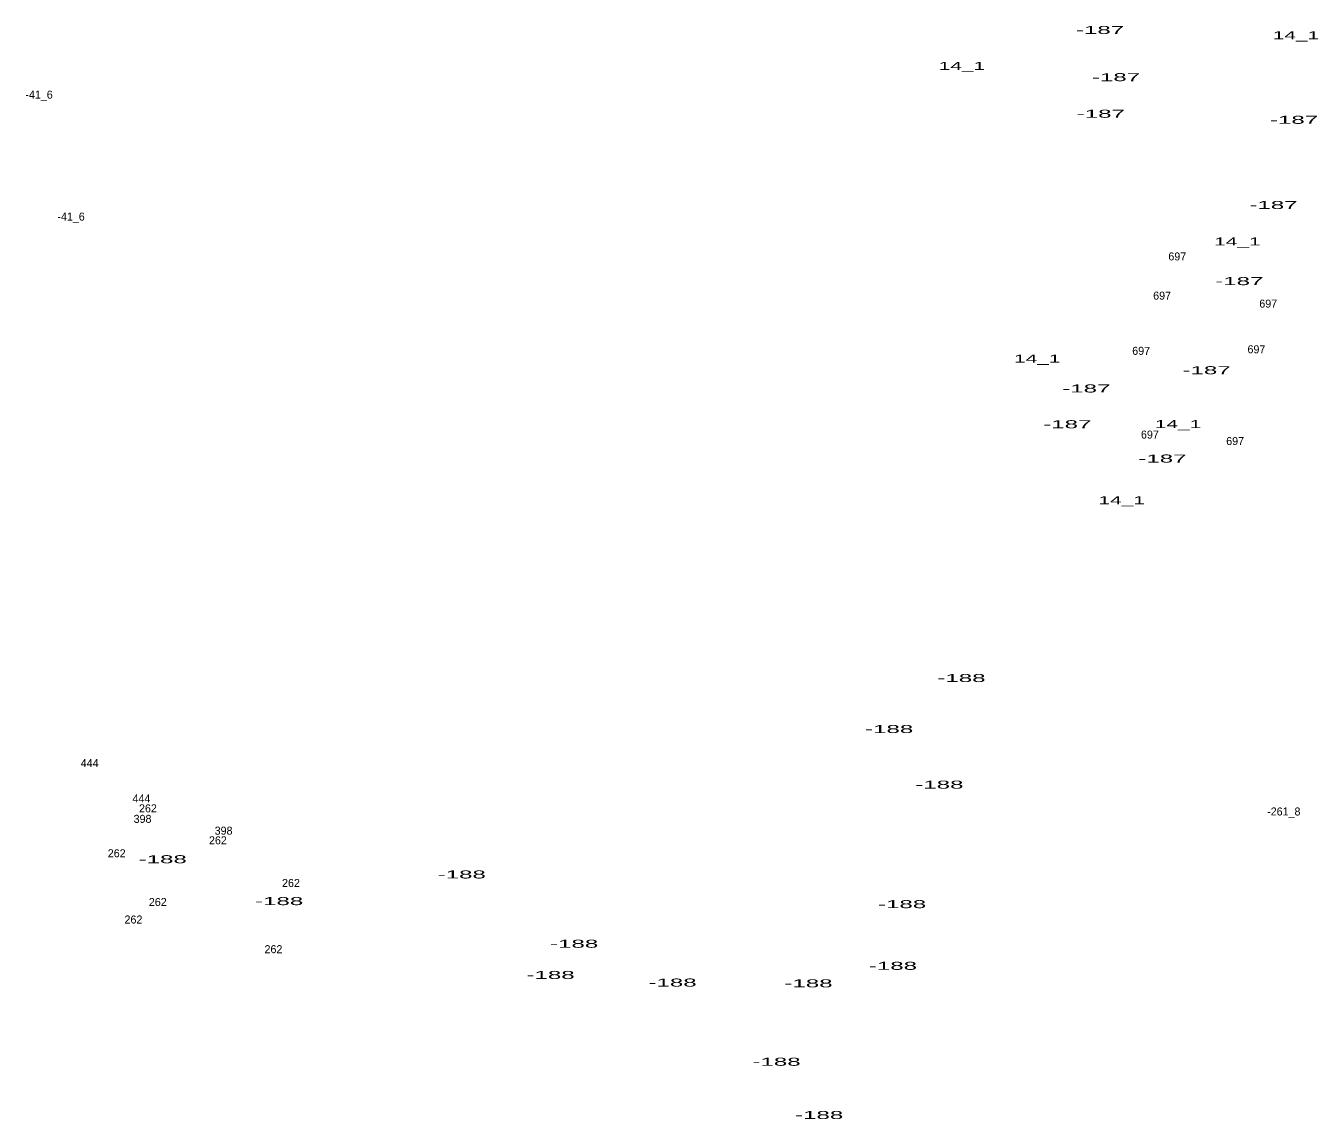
# Model space of a CAD drawing. Extents: x -658595 to -655205, y -1004347 to -1000147.
# Drawn here: x -656427 to -655781, y -1003837 to -1003291 of the extents above; entities that cross this region are included whole.
import ezdxf
from ezdxf.enums import TextEntityAlignment as Align

# ---------------------------------------------------------------- set-up
doc = ezdxf.new("R2010")
doc.units = 0
doc.header["$LTSCALE"] = 1.6
doc.layers.add('24', color=7, linetype='Continuous')

msp = doc.modelspace()

# ---------------------------------------------------------------- texts
at = {"layer": '24'}
for s, width, p in [('-187', 2.25, (-655890.235, -1003295.14)), ('14_1', 1.95, (-655792.301, -1003297.77)), ('14_1', 1.95, (-655959.281, -1003313.07)), ('-187', 2.25, (-655882.245, -1003318.73)), ('-187', 2.25, (-655889.855, -1003337)), ('-187', 2.25, (-655793.245, -1003340.04)), ('-187', 2.25, (-655803.515, -1003382.61)), ('14_1', 1.95, (-655821.591, -1003400.85)), ('-187', 2.25, (-655820.625, -1003420.66)), ('14_1', 1.95, (-655921.621, -1003459.36)), ('-187', 2.25, (-655836.985, -1003465.18)), ('-187', 2.25, (-655897.085, -1003474.31)), ('-187', 2.25, (-655906.595, -1003492.19)), ('14_1', 1.95, (-655851.251, -1003492.11)), ('-187', 2.25, (-655859.045, -1003509.32)), ('14_1', 1.95, (-655879.401, -1003530.13)), ('-188', 2.25, (-655959.521, -1003619.02)), ('-188', 2.25, (-655995.651, -1003644.51)), ('-188', 2.25, (-655970.551, -1003672.29)), ('-188', 2.25, (-656358.781, -1003709.58)), ('-188', 2.25, (-656209.301, -1003717.19)), ('-188', 2.25, (-656300.581, -1003730.51)), ('-188', 2.25, (-655989.181, -1003732.03)), ('-188', 2.25, (-656153.121, -1003751.81)), ('-188', 2.25, (-655993.751, -1003762.85)), ('-188', 2.25, (-656164.911, -1003767.41)), ('-188', 2.25, (-656103.941, -1003771.22)), ('-188', 2.25, (-656035.971, -1003771.6)), ('-188', 2.25, (-656051.941, -1003810.79)), ('-188', 2.25, (-656030.641, -1003837.42))]:
    msp.add_text(s, height=4, dxfattribs=dict(at, width=width)).set_placement(p, align=Align.CENTER)
for s, p in [('-41_6', (-656420.606, -1003327.47)), ('-41_6', (-656404.606, -1003388.42)), ('697', (-655851.623, -1003408.31)), ('697', (-655859.223, -1003427.91)), ('697', (-655806.163, -1003431.9)), ('697', (-655812.063, -1003454.73)), ('697', (-655869.683, -1003455.5)), ('697', (-655865.313, -1003497.35)), ('697', (-655822.713, -1003500.59)), ('444', (-656395.29, -1003661.52)), ('444', (-656369.43, -1003679.21)), ('262', (-656366.193, -1003684.15)), ('-261_8', (-655798.392, -1003685.72)), ('398', (-656368.873, -1003689.4)), ('262', (-656331.203, -1003700.13)), ('398', (-656328.363, -1003695.3)), ('262', (-656381.793, -1003706.6)), ('262', (-656294.683, -1003721.44)), ('262', (-656361.253, -1003730.95)), ('262', (-656373.423, -1003739.7)), ('262', (-656303.433, -1003754.54))]:
    msp.add_text(s, height=4, dxfattribs=at).set_placement(p, align=Align.CENTER)

doc.saveas('drawing.dxf')
